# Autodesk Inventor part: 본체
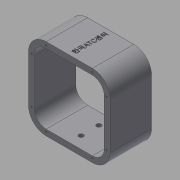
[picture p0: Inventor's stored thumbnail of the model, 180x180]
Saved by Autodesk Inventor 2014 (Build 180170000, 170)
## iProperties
Created: 2016-12
Part Number: 본체
Material: 일반
Document SubType Name: Modeling
Designer: mduedu
Density: 1 g/cm^3
Appearance: 기본값
Author: mduedu
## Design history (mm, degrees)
sketch "스케치1"
  geometry: L1 (-46, 42)-(-46, -36); L2 (-16, 72)-(62, 72); L3 (92, 42)-(92, -36); L4 (62, -66)-(-16, -66); A1 r 30 centre (-16, -36) between (-46, -36) and (-16, -66); A2 r 30 centre (62, 42) between (92, 42) and (62, 72); A3 r 30 centre (62, -36) between (62, -66) and (92, -36); A4 r 30 centre (-16, 42) between (-16, 72) and (-46, 42); 1 further point
  constraints: 8 end point, 8 point on circle, 8 tangent, 4 centre point, 3 equal radius, 1 horizontal, 1 perpendicular, 1 vertical
  dimensions: "d83" = 30 radius of A2; "d84" = 92 distance from line of L3 point (0, 0); "d85" = 138 distance between parallel lines of L4 L2; "d86" = 46 distance from line of L1 point (0, 0); "d87" = 72 distance from line of point (0, 0) L2
extrude "돌출1" new body sketch "스케치1" stored distance "d3" = 70; taper "d4" = 0 deg
feature "쉘1" dims "d5" = 10
sketch "스케치10"
  geometry: L1 (78, 70)-(0, 70) reference; L2 (-30, 70)-(-30, 0) reference; 4 further points
  constraints: 1 coincident, 1 horizontal alignment, 1 midpoint, 1 vertical alignment, 1 other
  dimensions: "d88" = 35 distance of point (39, 35) point (39, 70) (derived); "d89" = 69 distance from line of point (39, 35) L2 (derived)
feature "엠보싱1" sketch "스케치10" dims "d61" = 0.5, "d62" = 0, "d83" = 30, "d84" = 92, "d85" = 138, "d86" = 46, "d87" = 72
sketch "스케치11"
  geometry: L1 (-36, -36)-(-36, 42) reference; L2 (-16, 62)-(62, 62) reference; L3 (82, 42)-(82, -36) reference; L4 (62, -56)-(-16, -56) reference; L5 (-16, -66)-(62, -66) reference; L6 (92, -36)-(92, 42) reference; L7 (62, 72)-(-16, 72) reference; L8 (-46, 42)-(-46, -36) reference; L9 (-16, 66)-(62, 66); L10 (86, 42)-(86, -36); L11 (62, -60)-(-16, -60); L12 (-40, -36)-(-40, 42); A1 r 20 centre (-16, -36) between (-36, -36) and (-16, -56) reference; A2 r 20 centre (-16, 42) between (-16, 62) and (-36, 42) reference; A3 r 20 centre (62, 42) between (82, 42) and (62, 62) reference; A4 r 20 centre (62, -36) between (62, -56) and (82, -36) reference; A5 r 30 centre (-16, -36) between (-46, -36) and (-16, -66) reference; A6 r 30 centre (62, -36) between (62, -66) and (92, -36) reference; A7 r 30 centre (62, 42) between (92, 42) and (62, 72) reference; A8 r 30 centre (-16, 42) between (-16, 72) and (-46, 42) reference; A9 r 24 centre (62, 42) between (86, 42) and (62, 66); A10 r 24 centre (62, -36) between (62, -60) and (86, -36); A11 r 24 centre (-16, -36) between (-40, -36) and (-16, -60); A12 r 24 centre (-16, 42) between (-16, 66) and (-40, 42); 8 further points
  constraints: 8 coincident, 8 end point, 8 point on circle, 4 centre point, 7 other
  dimensions: "d90" = 6 distance between parallel lines of L9 L7
hole "구멍3" sketch "스케치11" at (-16, 66), (-40, 42), (-40, -36), (-16, -60), (62, -60), (86, -36), (86, 42), (62, 66) diameter "d63" = 3.242; stored, may be unused: countersink angle "d67" = 90 deg, drill point angle "d69" = 120 deg; dims "d64" = 8.6, "d65" = 4, "d66" = 2, "d68" = 10.6
sketch "스케치12"
  geometry: L1 (16, -56)-(-62, -56) reference; L2 (-82, -36)-(-82, 42) reference; L3 (-62, 62)-(16, 62) reference; L4 (36, 42)-(36, -36) reference; L5 (46, -36)-(46, 42) reference; L6 (16, 72)-(-62, 72) reference; L7 (-92, 42)-(-92, -36) reference; L8 (-62, -66)-(16, -66) reference; L9 (-62, 66)-(16, 66); L10 (40, 42)-(40, -36); L11 (16, -60)-(-62, -60); L12 (-86, -36)-(-86, 42); A1 r 20 centre (16, -36) between (16, -56) and (36, -36) reference; A2 r 20 centre (-62, -36) between (-82, -36) and (-62, -56) reference; A3 r 20 centre (-62, 42) between (-62, 62) and (-82, 42) reference; A4 r 20 centre (16, 42) between (36, 42) and (16, 62) reference; A5 r 30 centre (16, -36) between (16, -66) and (46, -36) reference; A6 r 30 centre (16, 42) between (46, 42) and (16, 72) reference; A7 r 30 centre (-62, 42) between (-62, 72) and (-92, 42) reference; A8 r 30 centre (-62, -36) between (-92, -36) and (-62, -66) reference; A9 r 24 centre (16, 42) between (40, 42) and (16, 66); A10 r 24 centre (16, -36) between (16, -60) and (40, -36); A11 r 24 centre (-62, -36) between (-86, -36) and (-62, -60); A12 r 24 centre (-62, 42) between (-62, 66) and (-86, 42); 8 further points
  constraints: 8 coincident, 8 end point, 8 point on circle, 4 centre point, 7 other
  dimensions: "d91" = 6 distance between parallel lines of L9 L6
hole "구멍5" sketch "스케치12" at (-62, 66), (-86, 42), (-86, -36), (-62, -60), (16, -60), (40, -36), (40, 42), (16, 66) diameter "d70" = 3.242; stored, may be unused: countersink angle "d74" = 90 deg, drill point angle "d76" = 120 deg; dims "d71" = 8.6, "d72" = 4, "d73" = 2, "d75" = 10.6
sketch "스케치15"
  geometry: L1 (135.6, -35)-(-57.6, -35) reference; L2 (78, 0)-(0, 0) reference; L3 (0, -70)-(78, -70) reference; L4 (39, 0)-(39, -70); C1 r 4 at (39, -20); C2 r 4 at (39, -50); 1 further point
  constraints: 2 centre point, 2 end point, 2 midpoint, 1 point on line, 1 symmetric about line, 1 other
  dimensions: "d92" = 8 diameter of C1; "d93" = 15 distance from line of C1.centre L1
extrude "돌출6" cut sketch "스케치15" stored distance "d94" = 10; taper "d95" = 0 deg
node "솔리드1"
node "투영된 루프3"
node "투영된 루프4"
